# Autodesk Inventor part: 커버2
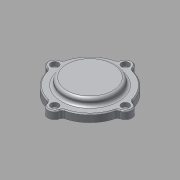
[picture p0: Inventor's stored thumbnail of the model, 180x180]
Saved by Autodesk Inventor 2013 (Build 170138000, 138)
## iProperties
Company: 한국ATC센터
Created: 2015-12
Part Number: 커버2
Document SubType Name: Modeling
Designer: mdu
Density: 2.71 g/cm^3
Material: 알루미늄 6061
Mass: 152.219 g
Surface Area: 146.729 cm^2
Volume: 56.1695 cm^3
Author: mdu
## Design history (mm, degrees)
sketch "스케치1"
  geometry: C1 r 1.621 at (0, 6.75) reference; C2 r 1.621 at (-37, -30.25) reference; C3 r 1.621 at (0, -67.25) reference; C4 r 1.621 at (37, -30.25) reference; C5 r 10 at (0, -30.25) reference; C6 r 12 at (0, -30.25); C7 r 24.5 at (0, -30.25) reference; A1 r 3 centre (-38.77, -20.408) between (-38.239, -23.361) and (-35.862, -21.146) reference; A2 r 7 centre (-37, -30.25) between (-38.239, -23.361) and (-38.239, -37.139) reference; A3 r 3 centre (-38.77, -40.092) between (-35.862, -39.354) and (-38.239, -37.139) reference; A4 r 37 centre (0, -30.25) between (-35.862, -39.354) and (-9.104, -66.113) reference; A5 r 3 centre (-9.842, -69.02) between (-6.889, -68.489) and (-9.104, -66.113) reference; A6 r 7 centre (0, -67.25) between (-6.889, -68.489) and (6.889, -68.489) reference; A7 r 3 centre (9.842, -69.02) between (9.104, -66.112) and (6.889, -68.489) reference; A8 r 37 centre (0, -30.25) between (9.104, -66.112) and (35.863, -39.354) reference; A9 r 3 centre (38.77, -40.092) between (38.239, -37.139) and (35.863, -39.354) reference; A10 r 7 centre (37, -30.25) between (38.239, -37.139) and (38.239, -23.361) reference; A11 r 3 centre (38.77, -20.408) between (35.863, -21.146) and (38.239, -23.361) reference; A12 r 37 centre (0, -30.25) between (35.863, -21.146) and (9.104, 5.612) reference; A13 r 3 centre (9.842, 8.52) between (6.889, 7.989) and (9.104, 5.612) reference; A14 r 7 centre (0, 6.75) between (6.889, 7.989) and (-6.889, 7.989) reference; A15 r 3 centre (-9.842, 8.52) between (-9.104, 5.612) and (-6.889, 7.989) reference; A16 r 37 centre (0, -30.25) between (-9.104, 5.612) and (-35.862, -21.146) reference; 1 further point
  constraints: 1 centre point, 1 coincident
  dimensions: "d2" = 2 radial gap between concentric circles of C6 C5
extrude "돌출1" new body sketch "스케치1" distance "d0" = 8; taper "d1" = 0 deg
sketch "스케치2"
  geometry: C1 r 23.5 at (0, -30.25) reference; C2 r 12 at (0, -30.25) reference; 1 further point
extrude "돌출2" join sketch "스케치2" distance "d4" = 5; taper "d5" = 0 deg
sketch "스케치3"
  geometry: C1 r 23.5 at (0, 0) reference; C2 r 20.5 at (0, 0); 1 further point
  constraints: 1 centre point
  dimensions: "d6" = 3 radial gap between concentric circles of C2 C1
node "작업 평면1"
extrude "돌출3" join sketch "스케치3" stored distance "d7" = 5; taper "d8" = 0 deg
fillet "모깎기1" dims "d9" = 3
sketch "스케치4"
  geometry: C1 r 12 at (0, -30.25) reference; C2 r 27 at (0, -30.25); 1 further point
  constraints: 1 centre point
  dimensions: "d10" = 15 radial gap between concentric circles of C1 C2
extrude "돌출4" join sketch "스케치4" distance "d11" = 7; taper "d12" = 0 deg
fillet "모깎기2" dims "d13" = 3
chamfer "모따기1" distance "d14" = 1; stored, may be unused: second distance "d15" = 2, angle "d16" = 45 deg
node "작업점1"
  node "작업축1"
chamfer "모따기2" distance "d24" = 1; stored, may be unused: second distance "d25" = 2, angle "d26" = 45 deg
hole "구멍6" diameter "d43" = 4.5; stored, may be unused: countersink angle "d47" = 90 deg, drill point angle "d49" = 118 deg; dims "d41" = 10, "d42" = 10, "d44" = 6, "d45" = 8, "d46" = 4.4, "d48" = 8
fillet "모깎기4" dims "d60" = 3
node "솔리드1"
pattern_circular "원형 패턴1" dims angle "d51" = 360 deg
node "참조1"
node "참조2"
